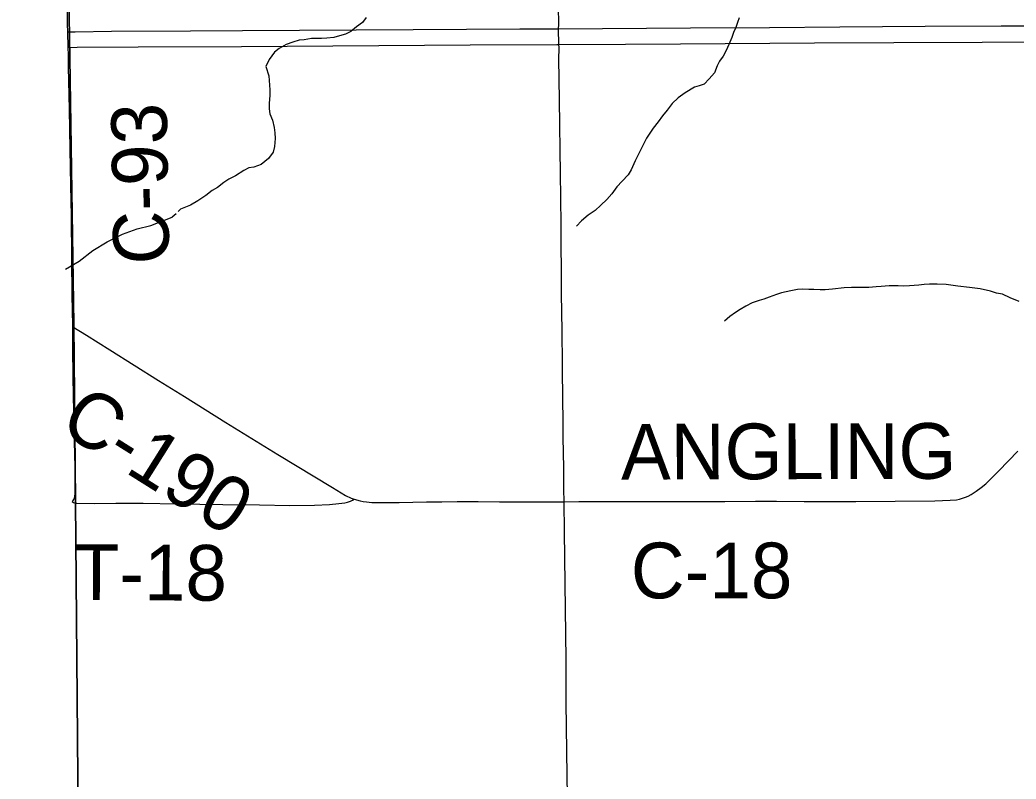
# Model space of a CAD drawing. Extents: x 1985906 to 2360102, y 891258 to 1222054.
# Drawn here: x 2071562 to 2076926, y 1010455 to 1014543 of the extents above; entities that cross this region are included whole.
import ezdxf

# ---------------------------------------------------------------- set-up
doc = ezdxf.new("R2010")
doc.units = 0
for name, color, linetype in [('GM_X_Adjacent_County', 7, 'Continuous'), ('GM_X_County', 7, 'Continuous'), ('GM_X_County_Road', 7, 'Continuous'), ('GM_X_County_Road_Text', 7, 'Continuous'), ('GM_X_Minor_River', 7, 'Continuous'), ('GM_X_Township', 7, 'Continuous'), ('GM_X_Township_Road', 7, 'Continuous'), ('GM_X_Township_Road_Text', 7, 'Continuous'), ('GM_X_US_Route', 7, 'Continuous')]:
    doc.layers.add(name, color=color, linetype=linetype)

msp = doc.modelspace()

# ---------------------------------------------------------------- linework, layer by layer
at = {"layer": 'GM_X_Adjacent_County'}
msp.add_lwpolyline([(2071926.7, 1054555.3), (2072166.7, 1051922.6), (2072218.3, 1051577.8), (2072142.8, 1047459), (2072178.7, 1046252), (2072112.2, 1041354.4), (2072120.2, 1038512.6), (2072055.1, 1036106.6), (2072018.3, 1033424.1), (2071939.9, 1030867.8), (2071602.1, 1025081.7), (2071562, 1025081.6), (2071696.9, 1021700.4), (2071829.8, 1014456.9), (2071852.3, 1012905.1), (2071861.2, 1011952), (2071887.5, 1008769)], dxfattribs=at)
at = {"layer": 'GM_X_County'}
msp.add_lwpolyline([(2071887.5, 1008769), (2071861.2, 1011952), (2071852.3, 1012905.1), (2071829.8, 1014456.9), (2071696.9, 1021700.4), (2071562, 1025081.6), (2071602.1, 1025081.7), (2071939.9, 1030867.8), (2072018.3, 1033424.1), (2072055.1, 1036106.6), (2072120.2, 1038512.6), (2072112.2, 1041354.4), (2072178.7, 1046252), (2072142.8, 1047459), (2072218.3, 1051577.8), (2072166.7, 1051922.6), (2071926.7, 1054555.3)], dxfattribs=at)
at = {"layer": 'GM_X_County_Road'}
for points in [[(2071819.8, 1014479.3), (2071818.5, 1014520.1), (2071819, 1014601.9)], [(2071822.5, 1014395.5), (2071819.8, 1014479.3)], [(2074492.5, 1011948.8), (2074491.4, 1012016.5), (2074490.5, 1012130.8), (2074487.6, 1012295.4), (2074487.1, 1012410.2), (2074486, 1012476), (2074482.9, 1012689.2), (2074482.2, 1012869.6), (2074478.1, 1013068.1), (2074477.6, 1013147.7), (2074475.6, 1013379.1), (2074476.4, 1013443.7), (2074475, 1013580.2), (2074473.5, 1013722.9), (2074471.7, 1013837), (2074469.3, 1013984.5), (2074466.3, 1014230.4), (2074464.3, 1014328.8), (2074464.8, 1014394.5), (2074464.1, 1014411.5)], [(2071846.2, 1012890.5), (2071846.1, 1012896.4), (2071843.1, 1013060.5), (2071841.5, 1013257.2), (2071839.2, 1013486.9), (2071836.6, 1013651), (2071833, 1013847.8), (2071828.1, 1014061), (2071823.9, 1014290.6), (2071823.8, 1014356.1), (2071822.5, 1014395.5)], [(2071844.2, 1011949.5), (2071849.6, 1011956.1), (2071852.7, 1011961.4), (2071855.9, 1011969.4), (2071857.7, 1011977.5), (2071858.9, 1011994.2), (2071859.9, 1012043.7), (2071858.8, 1012135.8), (2071854.2, 1012338.9), (2071849.1, 1012617.7), (2071846.6, 1012781.6), (2071846.2, 1012890.5)], [(2071846.2, 1012890.5), (2071920.4, 1012845.5), (2072045.6, 1012766.2), (2072308.7, 1012602.1), (2072448.7, 1012514.6), (2072670.8, 1012374.7), (2072950.9, 1012203.8), (2073245, 1012024.5), (2073315.9, 1011982.9), (2073346.4, 1011968.4), (2073361.2, 1011962)], [(2074492.5, 1011948.8), (2074570.5, 1011949.3), (2074767.3, 1011949.3), (2075029.9, 1011949.9), (2075176.6, 1011950.4), (2075358, 1011950.5), (2075522, 1011951.9), (2075636.1, 1011951.4), (2075784.4, 1011950), (2075964.3, 1011949.3), (2076063.3, 1011949.3), (2076275.3, 1011951.8), (2076488.4, 1011953.9), (2076570.2, 1011957), (2076604.5, 1011959.8), (2076620.8, 1011963.1), (2076637, 1011967.4), (2076652.7, 1011972.9), (2076668.1, 1011979.5), (2076683, 1011987.1), (2076711.1, 1012004.9), (2076737.6, 1012024.8), (2076761.9, 1012046), (2076832.3, 1012115.3), (2076934.4, 1012221.6)], [(2073361.2, 1011962), (2073394.3, 1011952.8), (2073409.4, 1011949.6), (2073427.6, 1011947.6), (2073456.1, 1011945), (2073505.5, 1011943.9), (2073603.2, 1011945.4), (2073751.5, 1011947.8), (2073833.5, 1011948.8), (2073915.4, 1011949.6), (2074029.7, 1011949.4), (2074144.2, 1011948.1), (2074273.7, 1011948), (2074455.8, 1011948.6), (2074492.5, 1011948.8)], [(2074513.1, 1010146.8), (2074508, 1010474.6), (2074506.4, 1010605.9), (2074503.8, 1010868), (2074502.8, 1011097.7), (2074498.1, 1011508), (2074494.6, 1011786.9), (2074492.5, 1011948.8)]]:
    msp.add_lwpolyline(points, dxfattribs=at)
at = {"layer": 'GM_X_Minor_River'}
for points in [[(2073426.1, 1014556.1), (2073406.2, 1014529.9), (2073374.2, 1014505.7), (2073344.3, 1014481.4), (2073314.3, 1014467.2), (2073282.3, 1014457), (2073252.3, 1014448.9), (2073214.2, 1014444.7), (2073186.2, 1014442.5), (2073132.1, 1014442.3), (2073092.1, 1014436.1), (2073066, 1014434), (2073032, 1014423.8), (2072996, 1014411.6), (2072958.1, 1014389.3), (2072932.1, 1014369.1), (2072904.3, 1014330.8), (2072886.4, 1014292.6), (2072902.7, 1014242.5), (2072904.9, 1014216.4), (2072907.1, 1014166.2), (2072907.3, 1014138.1), (2072903.5, 1014093.9), (2072903.7, 1014063.8), (2072907.8, 1014037.8), (2072922, 1014003.7), (2072930.2, 1013963.6), (2072934.4, 1013935.5), (2072936.6, 1013905.4), (2072932.8, 1013861.2), (2072924.9, 1013831), (2072901.1, 1013796.8), (2072861.2, 1013764.5), (2072821.2, 1013750.3), (2072795.1, 1013746.1), (2072767.2, 1013732), (2072723.2, 1013703.7), (2072687.3, 1013685.4), (2072659.3, 1013667.2), (2072625.4, 1013641), (2072597.4, 1013624.8), (2072563.5, 1013598.5), (2072519.6, 1013568.2), (2072479.6, 1013545.9), (2072427, 1013523.7), (2072414.1, 1013512.2)], [(2075433.9, 1014555.3), (2075426, 1014529.2), (2075416.1, 1014503), (2075404.3, 1014474.9), (2075394.4, 1014448.7), (2075378.5, 1014410.5), (2075364.7, 1014378.3), (2075348.8, 1014348.1), (2075328.9, 1014321.9), (2075317, 1014295.8), (2075301.2, 1014257.6), (2075273.3, 1014225.3), (2075245.4, 1014197.1), (2075219.4, 1014188.9), (2075193.4, 1014180.8), (2075143.5, 1014150.4), (2075105.5, 1014124.2), (2075073.6, 1014093.9), (2075047.8, 1014057.7), (2075021.9, 1014027.4), (2074998, 1013995.2), (2074972.1, 1013960.9), (2074936.4, 1013906.6), (2074910.6, 1013856.3), (2074874.9, 1013783.8), (2074853.1, 1013735.6), (2074837.2, 1013709.4), (2074805.3, 1013675.1), (2074775.4, 1013644.9), (2074749.6, 1013606.6), (2074721.7, 1013576.4), (2074689.8, 1013546.1), (2074659.9, 1013517.8), (2074621.9, 1013491.6), (2074586, 1013461.3), (2074558.1, 1013433.1)], [(2072403.3, 1013499.3), (2072381.3, 1013481)], [(2071807.1, 1013200.8), (2071880.8, 1013243.9), (2071955.4, 1013301.7), (2072032, 1013347.4), (2072114.6, 1013389.1), (2072193.1, 1013418.8), (2072267.5, 1013436.5), (2072381.3, 1013481)], [(2076942.8, 1013026.5), (2076894.6, 1013046.3), (2076852.4, 1013066.2), (2076820.3, 1013072.1), (2076788.2, 1013082), (2076732, 1013095.8), (2076673.9, 1013101.5), (2076611.8, 1013109.3), (2076549.6, 1013119), (2076501.5, 1013120.8), (2076459.4, 1013120.6), (2076431.4, 1013118.5), (2076401.3, 1013114.3), (2076351.2, 1013112.1), (2076321.2, 1013109.9), (2076291.1, 1013111.8), (2076243, 1013111.6), (2076199, 1013107.4), (2076172.9, 1013105.2), (2076132.9, 1013103), (2076038.7, 1013102.6), (2076000.6, 1013100.4), (2075936.5, 1013094.1), (2075898.5, 1013089.9), (2075870.4, 1013089.8), (2075836.4, 1013091.6), (2075810.3, 1013091.5), (2075778.2, 1013093.4), (2075748.2, 1013091.2), (2075712.2, 1013085), (2075662.1, 1013072.8), (2075636.1, 1013064.6), (2075596.1, 1013050.4), (2075568.1, 1013040.2), (2075542.1, 1013032.1), (2075504.1, 1013019.8), (2075470.1, 1013001.6), (2075440.2, 1012983.4), (2075414.2, 1012967.2), (2075384.3, 1012947), (2075356.4, 1012920.8)]]:
    msp.add_lwpolyline(points, dxfattribs=at)
at = {"layer": 'GM_X_Township'}
msp.add_lwpolyline([(2071887.5, 1008769), (2071861.2, 1011952), (2071852.3, 1012905.1), (2071829.8, 1014456.9), (2071696.9, 1021700.4), (2071562, 1025081.6), (2071602.1, 1025081.7), (2074264, 1025122.4), (2076405.9, 1025155.2), (2079654.5, 1025204.9), (2081728.4, 1025236.6), (2086577.8, 1025306.1), (2087095.5, 1025303.4), (2089225.7, 1025330.9), (2092097.4, 1025367.8), (2095094.6, 1025388.3)], dxfattribs=at)
at = {"layer": 'GM_X_Township_Road'}
for points in [[(2074462.7, 1014496.1), (2074462.9, 1014518), (2074462.9, 1014553), (2074462.3, 1014581.9), (2074461.4, 1014663.9), (2074460.2, 1014795.3), (2074458.4, 1014912), (2074456.4, 1015090.3), (2074449.8, 1015418.5), (2074441.9, 1015664.6), (2074437.1, 1015865), (2074431.3, 1016140.6), (2074427.7, 1016403.2), (2074424.2, 1016665.8), (2074420.5, 1016977.7), (2074416.4, 1017191.1), (2074414, 1017371.7), (2074413.1, 1017672.4), (2074412.3, 1018229.8), (2074410.5, 1018491.8), (2074410.9, 1018898.5), (2074407.9, 1019277.9), (2074406.2, 1019610), (2074404.4, 1019985.1)], [(2074464.1, 1014411.5), (2074462.7, 1014496.1)], [(2071844.2, 1011949.5), (2071850.8, 1011945.4), (2071855.5, 1011943.1), (2071859.9, 1011942), (2071864.4, 1011941.7), (2071867.6, 1011941.6), (2071962.4, 1011938.8), (2072078.1, 1011940.3), (2072226.3, 1011940.9), (2072406.8, 1011938.2), (2072654.3, 1011934.3), (2072851.7, 1011931.9), (2073015.3, 1011929.2), (2073147.7, 1011929.7), (2073229.4, 1011933.3), (2073279.2, 1011938.5), (2073311.7, 1011943.1), (2073326.1, 1011946.6), (2073342, 1011951.7), (2073352.4, 1011956.9), (2073361.2, 1011962)]]:
    msp.add_lwpolyline(points, dxfattribs=at)
at = {"layer": 'GM_X_US_Route'}
for points in [[(2071819.8, 1014479.3), (2071859.5, 1014479.9), (2072054.5, 1014482.7), (2072481, 1014484.5), (2072760, 1014486.3), (2073678.8, 1014491.6), (2074253, 1014494.7), (2074434, 1014495.9), (2074462.7, 1014496.1), (2075171.9, 1014501), (2075598.4, 1014502.9), (2075975.9, 1014506), (2076435.3, 1014509.1), (2076845.6, 1014511.6), (2077157.3, 1014512)], [(2071822.5, 1014395.5), (2071870, 1014395.9), (2072198.1, 1014398.6), (2072755.8, 1014400.7), (2073986.2, 1014409), (2074452.1, 1014411.4), (2074464.1, 1014411.5), (2074823, 1014413.3), (2075118.2, 1014415), (2075840.1, 1014419.2), (2076266.7, 1014422.1), (2076742.5, 1014424), (2077497.3, 1014428.5)]]:
    msp.add_lwpolyline(points, dxfattribs=at)

# ---------------------------------------------------------------- texts
at = {"layer": 'GM_X_County_Road_Text'}
for s, rotation, p in [('C-93', 90.9033, (2072365.9, 1013228.6)), ('C-190', 327.823, (2071762.7, 1012336.7)), ('ANGLING', 0.1478, (2074798.8, 1012067.8)), ('C-18', 0, (2074851.4, 1011428.5))]:
    msp.add_text(s, height=300, rotation=rotation, dxfattribs=at).set_placement(p)
at = {"layer": 'GM_X_Township_Road_Text'}
msp.add_text('T-18', height=300, rotation=359.6491, dxfattribs=at).set_placement((2071851, 1011420.2))

doc.saveas('drawing.dxf')
